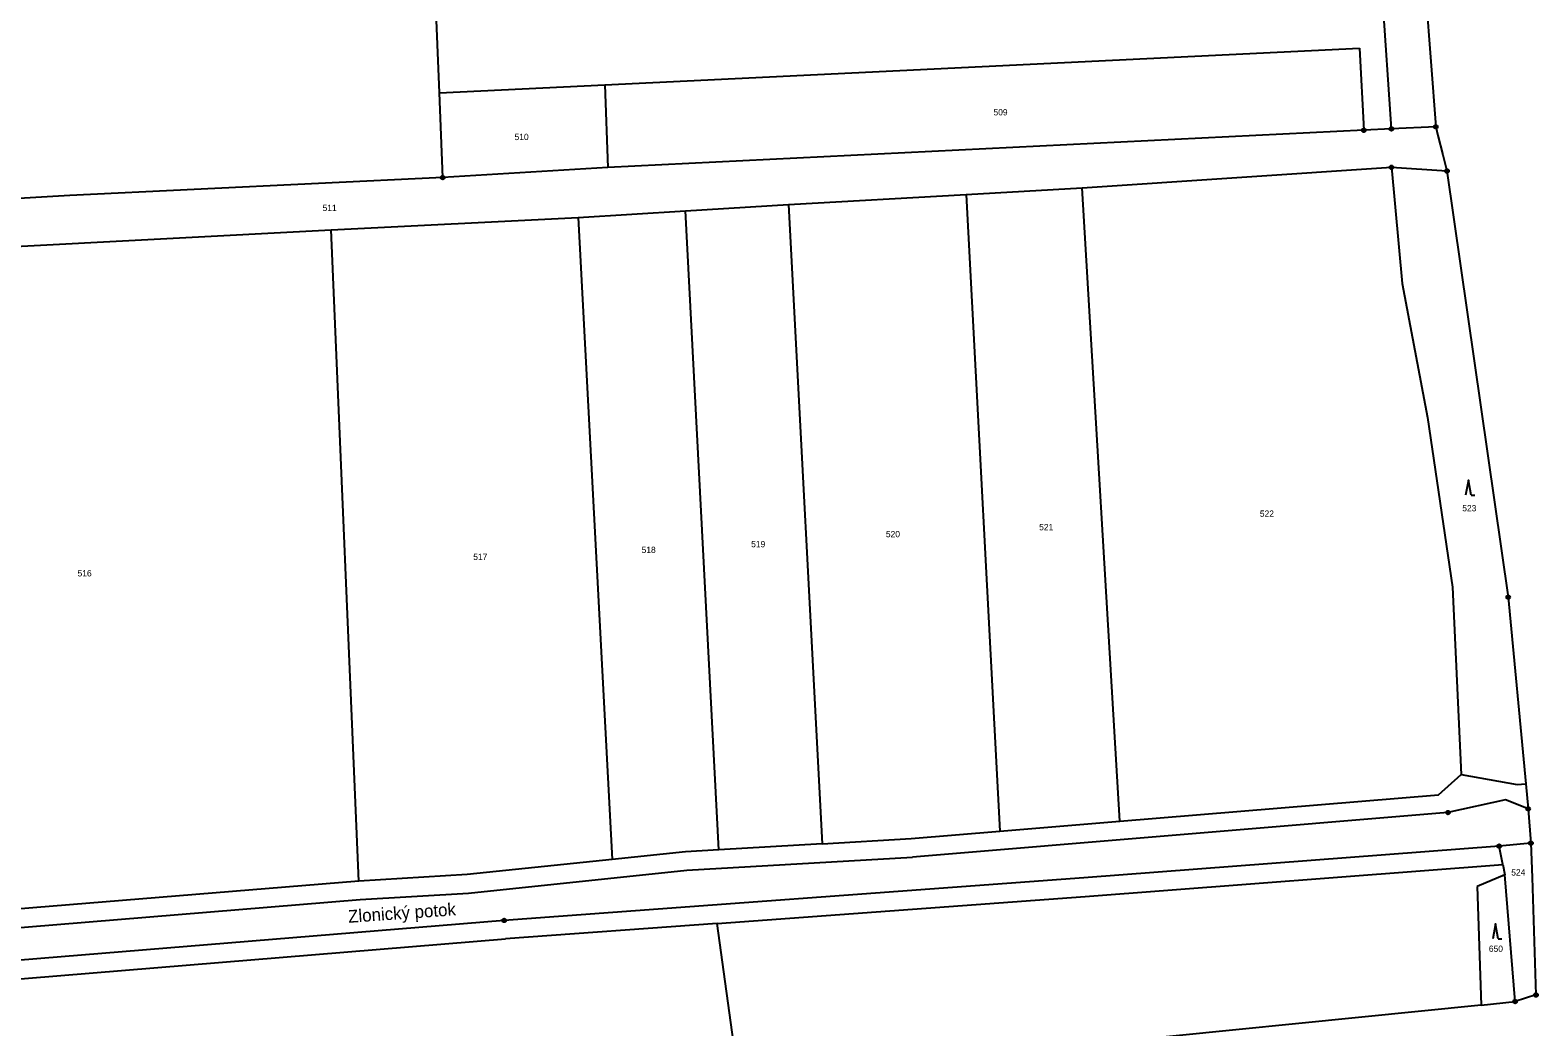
# Model space of a CAD drawing. Extents: x -759947 to -757003, y -1019641 to -1017100.
# Drawn here: x -757569.9 to -757163.9, y -1019238.4 to -1018970.1 of the extents above; entities that cross this region are included whole.
import ezdxf

# ---------------------------------------------------------------- set-up
doc = ezdxf.new("R2010")
doc.units = 0
doc.header["$LTSCALE"] = 0.68
for name, color, linetype, lineweight in [('1', 7, 'Continuous', 25), ('3', 7, 'Continuous', 25), ('7', 7, 'Continuous', 13), ('8', 7, 'Continuous', 25)]:
    doc.layers.add(name, color=color, linetype=linetype, lineweight=lineweight)
doc.layers.add('2', color=7, linetype='Continuous')

msp = doc.modelspace()

# ---------------------------------------------------------------- linework, layer by layer
at = {"layer": '1'}
for p, q in [((-757199.04, -1018896.04), (-757191.43, -1018996.12)), ((-757203.38, -1018996.71), (-757208.88, -1018912.58)), ((-757459.75, -1018986.96), (-757462.16, -1018924.96)), ((-757313.57, -1018979.9), (-757211.92, -1018974.99)), ((-757211.92, -1018974.99), (-757210.8, -1018997.07)), ((-757415.22, -1018984.81), (-757313.57, -1018979.9)), ((-757459.75, -1018986.96), (-757415.22, -1018984.81)), ((-757458.86, -1019009.81), (-757459.75, -1018986.96)), ((-757415.22, -1018984.81), (-757414.35, -1019007.07)), ((-757191.43, -1018996.12), (-757203.38, -1018996.71)), ((-757191.43, -1018996.12), (-757190.82, -1018998.5)), ((-757210.8, -1018997.07), (-757312.57, -1019002.07)), ((-757203.38, -1018996.71), (-757210.8, -1018997.07)), ((-757190.82, -1018998.5), (-757189.5, -1019003.71)), ((-757312.57, -1019002.07), (-757414.35, -1019007.07)), ((-757189.5, -1019003.71), (-757188.4, -1019008.02)), ((-757414.35, -1019007.07), (-757458.86, -1019009.81)), ((-757286.65, -1019012.58), (-757203.36, -1019007.04)), ((-757203.36, -1019007.04), (-757188.4, -1019008.02)), ((-757203.36, -1019007.04), (-757200.49, -1019038.32)), ((-757188.4, -1019008.02), (-757171.91, -1019122.73)), ((-757458.86, -1019009.81), (-757559.23, -1019014.66)), ((-757317.88, -1019014.35), (-757286.65, -1019012.58)), ((-757276.53, -1019183.06), (-757286.65, -1019012.58)), ((-757559.23, -1019014.66), (-757703.19, -1019022.77)), ((-757365.7, -1019017.06), (-757317.88, -1019014.35)), ((-757317.88, -1019014.35), (-757308.86, -1019185.75)), ((-757488.89, -1019023.89), (-757422.33, -1019020.58)), ((-757422.33, -1019020.58), (-757393.51, -1019018.79)), ((-757422.33, -1019020.58), (-757413.19, -1019193.34)), ((-757393.51, -1019018.79), (-757365.7, -1019017.06)), ((-757384.46, -1019190.75), (-757393.51, -1019018.79)), ((-757365.7, -1019017.06), (-757356.64, -1019189.13)), ((-757630.83, -1019031.38), (-757488.89, -1019023.89)), ((-757481.46, -1019199.17), (-757488.89, -1019023.89)), ((-757200.49, -1019038.32), (-757193.65, -1019074.38)), ((-757193.65, -1019074.38), (-757186.95, -1019120.03)), ((-757186.95, -1019120.03), (-757184.55, -1019170.47)), ((-757171.91, -1019122.73), (-757167.15, -1019172.95)), ((-757190.71, -1019175.93), (-757184.55, -1019170.47)), ((-757184.55, -1019170.47), (-757169.51, -1019173.17)), ((-757169.51, -1019173.17), (-757167.15, -1019172.95)), ((-757167.15, -1019172.95), (-757166.51, -1019179.71)), ((-757276.53, -1019183.06), (-757190.71, -1019175.93)), ((-757172.62, -1019177.31), (-757188.13, -1019180.72)), ((-757166.51, -1019179.71), (-757172.62, -1019177.31)), ((-757188.13, -1019180.72), (-757332.34, -1019192.72)), ((-757308.86, -1019185.75), (-757276.53, -1019183.06)), ((-757166.51, -1019179.71), (-757165.78, -1019188.97)), ((-757332.69, -1019187.73), (-757308.86, -1019185.75)), ((-757393.5, -1019191.28), (-757413.19, -1019193.34)), ((-757384.46, -1019190.75), (-757393.5, -1019191.28)), ((-757356.64, -1019189.13), (-757384.46, -1019190.75)), ((-757356.64, -1019189.13), (-757332.69, -1019187.73)), ((-757174.36, -1019189.74), (-757286.2, -1019198.34)), ((-757165.78, -1019188.97), (-757174.36, -1019189.74)), ((-757173.36, -1019194.68), (-757174.36, -1019189.74)), ((-757165.78, -1019188.97), (-757165.48, -1019198.17)), ((-757413.19, -1019193.34), (-757452.28, -1019197.43)), ((-757393.09, -1019196.26), (-757332.34, -1019192.72)), ((-757285.82, -1019203.33), (-757173.36, -1019194.68)), ((-757173.36, -1019194.68), (-757172.79, -1019197.47)), ((-757481.46, -1019199.17), (-757585.44, -1019207.69)), ((-757452.28, -1019197.43), (-757481.46, -1019199.17)), ((-757451.87, -1019202.41), (-757393.09, -1019196.26)), ((-757286.2, -1019198.34), (-757442.32, -1019209.75)), ((-757172.79, -1019197.47), (-757180.31, -1019200.67)), ((-757170.06, -1019231.58), (-757172.79, -1019197.47)), ((-757165.48, -1019198.17), (-757164.43, -1019229.83)), ((-757481.11, -1019204.16), (-757451.87, -1019202.41)), ((-757384.96, -1019210.58), (-757285.82, -1019203.33)), ((-757180.31, -1019200.67), (-757179.15, -1019232.55)), ((-757585.17, -1019212.69), (-757481.11, -1019204.16)), ((-757442.32, -1019209.75), (-757586.4, -1019221.58)), ((-757384.96, -1019210.58), (-757441.93, -1019214.74)), ((-757367.57, -1019335.6), (-757384.96, -1019210.58)), ((-757586.12, -1019226.57), (-757441.93, -1019214.74)), ((-757179.15, -1019232.55), (-757170.06, -1019231.58)), ((-757164.43, -1019229.83), (-757170.06, -1019231.58)), ((-757179.15, -1019232.55), (-757295.25, -1019244.26))]:
    msp.add_line(p, q, dxfattribs=at)
at = {"layer": '3'}
for p, q in [((-757181.88, -1019095.29), (-757180.884, -1019095.29)), ((-757174.59, -1019214.72), (-757173.594, -1019214.72))]:
    msp.add_line(p, q, dxfattribs=at)
for points in [[(-757181.88, -1019095.29), (-757182.63, -1019091.29), (-757183.38, -1019095.29)], [(-757174.59, -1019214.72), (-757175.34, -1019210.72), (-757176.09, -1019214.72)]]:
    msp.add_lwpolyline(points, dxfattribs=at)
at = {"layer": '8'}
for centre, radius in [((-757203.38, -1018996.7099), 0.5), ((-757191.43, -1018996.1199), 0.5), ((-757191.43, -1018996.1199), 0.0303), ((-757210.8, -1018997.0699), 0.5), ((-757210.8, -1018997.0699), 0.0303), ((-757203.38, -1018996.7099), 0.0303), ((-757203.36, -1019007.0399), 0.5), ((-757203.36, -1019007.0399), 0.0303), ((-757188.4, -1019008.0199), 0.5), ((-757188.4, -1019008.0199), 0.0303), ((-757458.86, -1019009.8099), 0.5), ((-757458.86, -1019009.8099), 0.0303), ((-757171.91, -1019122.7299), 0.5), ((-757171.91, -1019122.7299), 0.0303), ((-757166.51, -1019179.7099), 0.5), ((-757188.13, -1019180.7199), 0.5), ((-757188.13, -1019180.7199), 0.0303), ((-757166.51, -1019179.7099), 0.0303), ((-757174.36, -1019189.7399), 0.5), ((-757174.36, -1019189.7399), 0.0303), ((-757165.78, -1019188.9699), 0.5), ((-757165.78, -1019188.9699), 0.0303), ((-757442.32, -1019209.7499), 0.5), ((-757442.32, -1019209.7499), 0.0303), ((-757170.06, -1019231.5799), 0.5), ((-757170.06, -1019231.5799), 0.0303), ((-757164.43, -1019229.8299), 0.5), ((-757164.43, -1019229.8299), 0.0303)]:
    msp.add_circle(centre, radius, dxfattribs=at)

# ---------------------------------------------------------------- texts
at = {"layer": '2'}
for s, p in [('509', (-757310.52, -1018993.065)), ('510', (-757439.5, -1018999.705)), ('511', (-757491.2, -1019018.815)), ('523', (-757184.28, -1019099.635)), ('522', (-757238.79, -1019101.115)), ('520', (-757339.5, -1019106.615)), ('521', (-757298.22, -1019104.745)), ('518', (-757405.28, -1019110.865)), ('519', (-757375.78, -1019109.315)), ('517', (-757450.63, -1019112.735)), ('516', (-757557.18, -1019117.165)), ('524', (-757171.09, -1019197.675)), ('650', (-757177.12, -1019218.225))]:
    msp.add_text(s, height=1.7, dxfattribs=at).set_placement(p)
at = {"layer": '7'}
msp.add_text('Zlonický potok', height=3.4, rotation=4, dxfattribs=at).set_placement((-757484.2, -1019210.417))

doc.saveas('drawing.dxf')
